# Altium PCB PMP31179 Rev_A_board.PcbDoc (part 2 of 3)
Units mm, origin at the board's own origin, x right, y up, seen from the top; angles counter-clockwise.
Board outline 218.44 x 102.26 mm, 4 copper layers (Top Layer, Mid-Layer 1, Mid-Layer 2, Bottom Layer), stack 1.473 mm thick; 246 components, 120 nets, 592 pads, 115 vias.
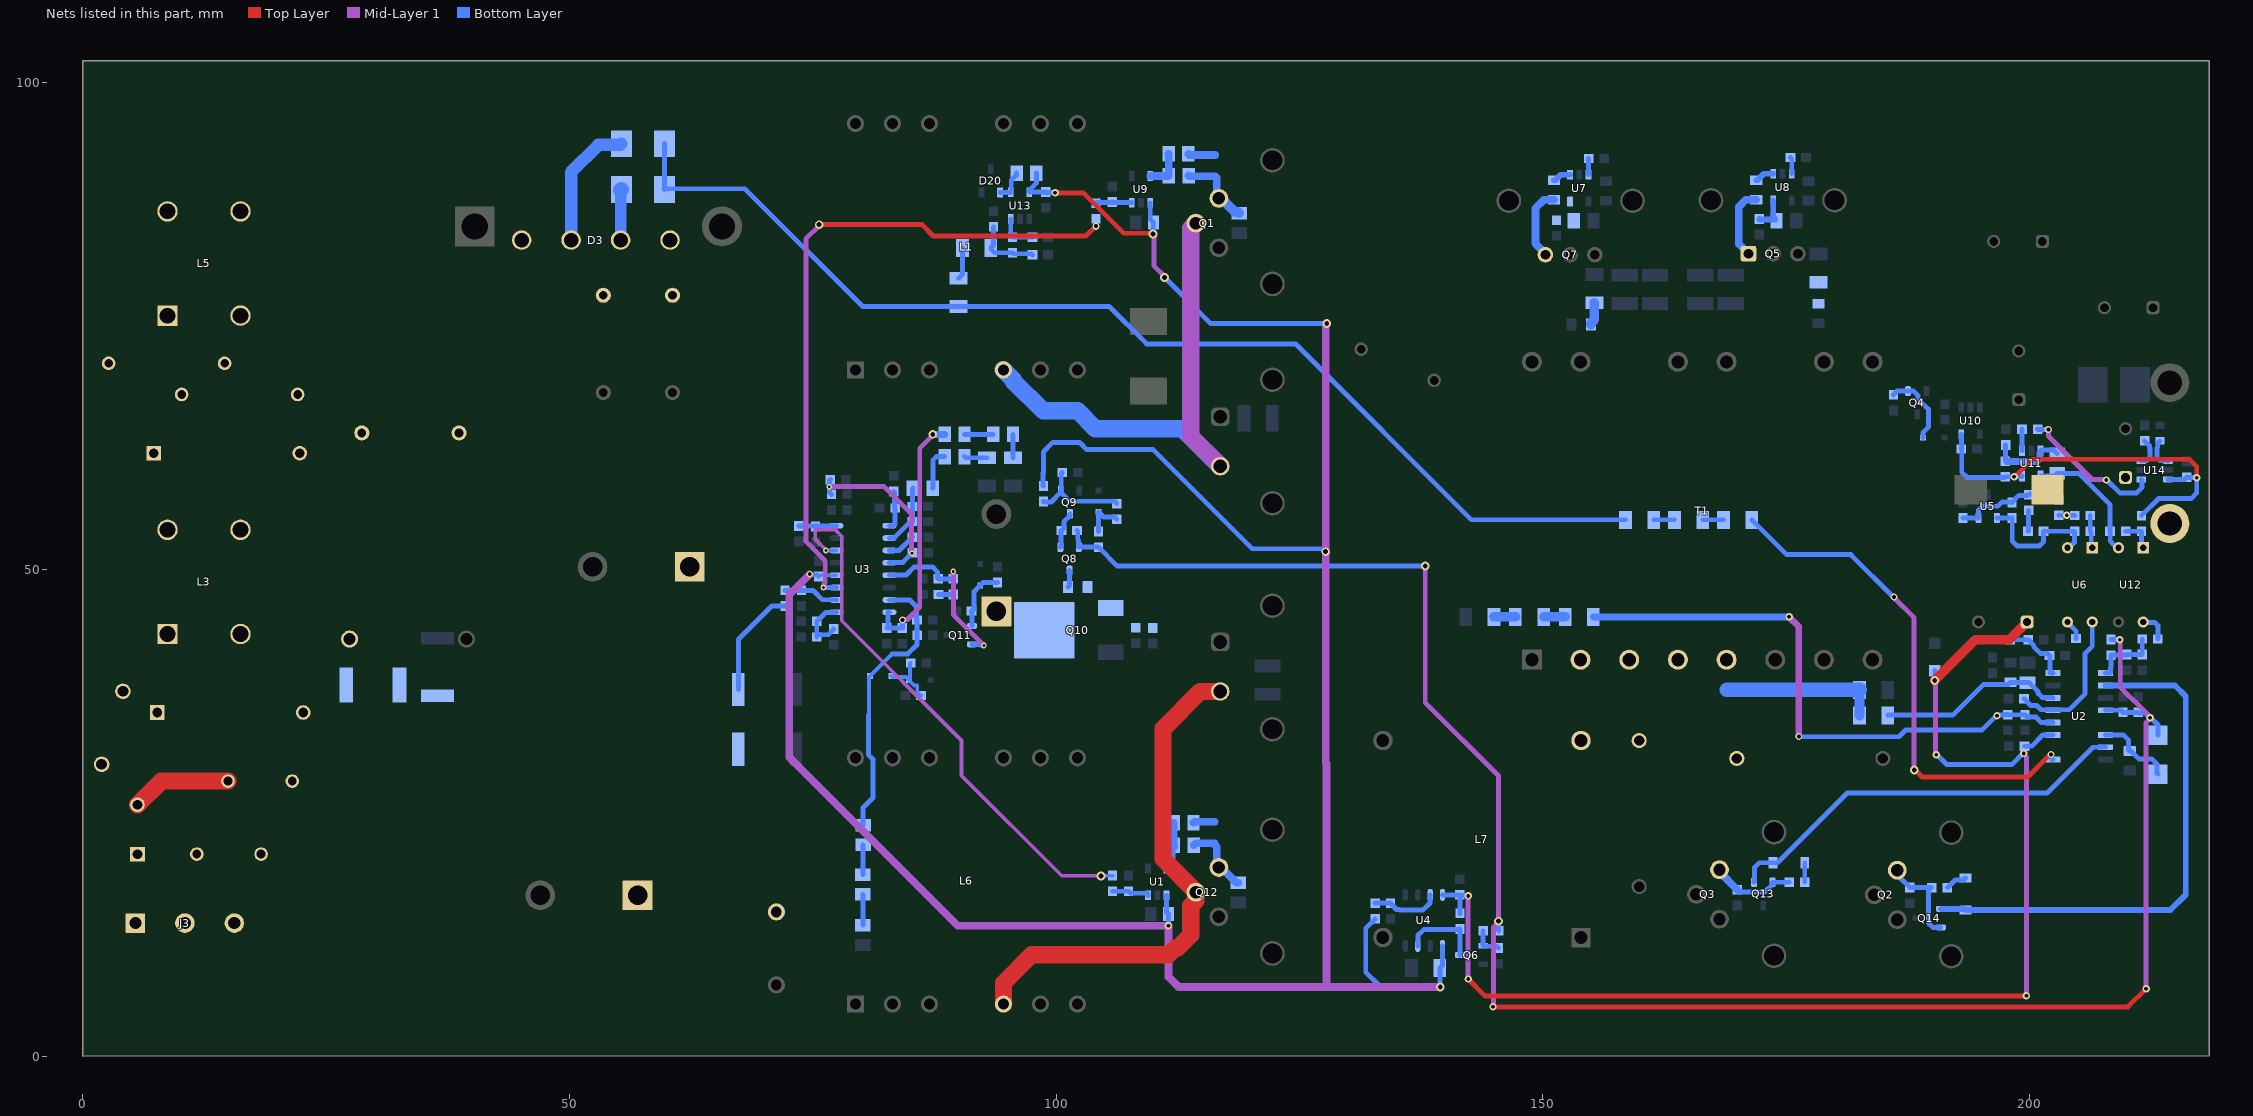
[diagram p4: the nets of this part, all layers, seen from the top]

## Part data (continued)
D20: library part CMP-0033016-1, "Precision Micropower Shunt Voltage Reference, 1% accuracy, 5 V, 15 ppm / degC, 15 mA, -40 to 125 degC, 3-pin SOT-23 (DBZ), Green (RoHS & no Sb/Br)", Manufacturer="Texas Instruments", Rating=Catalog, Temp Coeff(Max)(ppm/ degree C)=150, Temp Coeff(Typ)(ppm/ degree C)=15
D100: library part CMP-0082070-2, "Diode, Switching, 600 V, 3 A, SMC", Manufacturer=Vishay-Semiconductor, Value2=1.15V
F1: "FUSE, BOARD MOUNT, 10 A, 300 V, TH-2P", Manufacturer="LITTELFUSE INC"
H1 H2 H3 H4 H5 H6: library part CMP-0003620-1, "Bumpon, Hemisphere, 0.44 X 0.20, Clear", Manufacturer=3M, PartNumber="SJ-5303 (CLEAR)", Supplier Part Number 1=SJ5303-7-ND
H7: library part CMP-0092962-1, "Heat Sink 11 K/W, 25,4x42x25 mm, black anodized, for TO-220", Manufacturer="Assmann WSW components", Mating Package=TO-220, Operating Temperature Range=to, Thermal Resistance Forced Air Flow=11°C/W
J3: library part CMP-0074911-1, "Terminal Block, 5.08 mm, 3x1, Brass, TH", Color=Blue, Current_A=15A, Manufacturer="On-Shore Technology", Supplier Part Number 1=ED1610-ND, Voltage_V=300V
L1 L6: library part CMP-0088743-1, "INDUCTOR", Manufacturer="Wurth Electronics", Operating Temperature Range="-40°C to +125°C", Voltage_Isolation_Vrms=1kV
L2: library part CMP-0064735-2, "Inductor, Toroid, Powdered Iron, 150 uH, 5 A, 0.045 ohm, TH", Manufacturer="Wurth Elektronik", Supplier Part Number 1=732-1427-ND, Value1="0.045 ohm", Value2=5A, ValueDisplayed=150uH
L3 L5: "FILTER, WE-CMBNC COMMON MODE POWER LINE CHOKE, 1mH, 15A, VERTICAL, TH-4P", Manufacturer="Wurth Elektronics"
L4: library part CMP-0062077-1, "Inductor, Ferrite, 300 nH, 32 A, 0.00031 ohm, SMD", Manufacturer="Pulse Engineering", Supplier Part Number 1=553-2161-1-ND, Value1="0.00031 ohm", Value2=32A, ValueDisplayed=300nH
L7: library part CMP-0088744-1, "INDUCTOR, 17uH, 20A", Manufacturer="Wurth Electronics", Operating Temperature Range="-40°C to +125°C", Test Frequency=10kHz, Tolerance_%=10%
L8: library part CMP-0064496-2, "Inductor, Drum Core, Ferrite, 22 uH, 0.7 A, 0.255 ohm, SMD", Manufacturer="Wurth Elektronik", Supplier Part Number 1=732-1337-1-ND, Value1="0.255 ohm", Value2=0.7A, ValueDisplayed=22uH
Logo2: library part CMP-0074840-1, "ESD Susceptible Symbol"
Logo3 LOGO9: library part CMP-0074837-1, "IEC 61010-1 Hot Surface Warning"
LOGO4 LOGO7 LOGO8 LOGO10: library part CMP-0074835-1, "IEC 61010-1 High Voltage Warning"
M1 M2 M3 M4 M5 M6 M7 M8: "HEATSINK, ALUMINIUM WITH CLIP, VERTICAL MOUNT, SOLDERABLE PIN, TO-220", Manufacturer=OHMITE
Q1 Q12: library part CMP-0001223-3, "MOSFET N-CHANNEL 600V 26A TO220", Alternate Manufacturer=None, Manufacturer="Infineon Technologies", Supplier Part Number 1=IPA60R120P7XKSA1-ND, Value2="37 nC"
Q2 Q3: library part CMP-0001223-3, "MOSFET N-CHANNEL 600V 26A TO220", Alternate Manufacturer=None, Manufacturer="Infineon Technologies", PartNumber=IPP60R070CFD7XKSA1, Supplier Part Number 1=IPP60R070CFD7XKSA1-ND, Value2="65 nC"
Q4: library part CMP-0000488-2, "Transistor, NPN, 60 V, 0.5 A, AEC-Q101, SOT-23", Manufacturer="ON Semiconductor", Supplier Part Number 1=MMBTA05LT1GOSCT-ND, Value1="0.5 A"
Q5 Q7: library part CMP-0000955-2, "MOSFET, N-CH, 100 V, 100 A, KCS0003B (TO-220-3)", Alternate Manufacturer=None, Manufacturer="Texas Instruments", Supplier Part Number 1=296-37480-5-ND, Value2="38 nC"
Q6: library part CMP-0000421-2, "Transistor, NPN, 30 V, 0.6 A, SOT-23", Manufacturer="ON Semiconductor", Supplier Part Number 1=MMBT2222LT1GOSCT-ND, Value1="0.6 A", Value2=300
Q8: library part CMP-0000011-2, "MOSFET, P-CH, -50 V, -0.13 A, SOT-23", Alternate Manufacturer=None, Manufacturer="Diodes Inc.", Supplier Part Number 1=BSS84-FDICT-ND
Q9: library part CMP-0000419-1, "Transistor, NPN, 40 V, 0.2 A, SOT-23", Manufacturer="ON Semiconductor", Supplier Part Number 1=MMBT3904LT1GOSCT-ND, Value1="0.2 A", Value2=300
Q10: library part CMP-0079555-2, "MOSFET, N-CH, 600 V, 9 A, DPAK", Alternate Manufacturer=None, Manufacturer="Infineon Technologies", Supplier Part Number 1=IPD60R360P7SAUMA1CT-ND, Value1="? ohm", Value2="13 nC"
Q11: library part CMP-0000326-1, "Transistor, PNP, 40 V, 0.2 A, SOT-23", Manufacturer="Diodes Inc.", Supplier Part Number 1=MMBT3906-FDICT-ND, Value1="0.2 A", Value2=400
Q13 Q14: library part CMP-0000317-2, "Transistor, PNP, 30 V, 0.1 A, SOT-23", Manufacturer="Diodes Inc.", Supplier Part Number 1=BC858C-7-F-ND, Value1="0.1 A", Value2=600
R1 R11: library part CMP-0023343-3, "RES, 0, 1%, 0.1 W, AEC-Q200 Grade 0, 0603", Manufacturer="Stackpole Electronics Inc", Power_W=100mW, Supplier Part Number 1=RMCF0603ZT0R00CT-ND, TempCo=ppm/C, Tolerance_%=1%, Value2=0.1W, Value_Code=0
R2: library part CMP-0022703-3, "RES, 4.53 k, 1%, 0.1 W, AEC-Q200 Grade 0, 0603", Manufacturer=Panasonic, Power_W=100mW, Supplier Part Number 1=P4.53KHCT-ND, TempCo="100 ppm/C", Tolerance_%=1%, Value2=0.1W, Value_Code=4k53, ValueDisplayed=4.53k
R3: library part CMP-0020904-3, "RES, 150, 1%, 0.125 W, AEC-Q200 Grade 0, 0805", Manufacturer=Vishay-Dale, Power_W=125mW, Supplier Part Number 1=541-150CCT-ND, TempCo="100 ppm/C", Tolerance_%=1%, Value2=0.125W, Value_Code=150R, ValueDisplayed=150
R4 R54: library part CMP-0020655-3, "RES, 18, 5%, 0.125 W, AEC-Q200 Grade 0, 0805", Manufacturer=Panasonic, Power_W=125mW, Supplier Part Number 1=P18ACT-ND, TempCo="200 ppm/C", Tolerance_%=5%, Value2=0.125W, Value_Code=18R0, ValueDisplayed=18
R5: library part CMP-0020941-3, "RES, 18.2, 1%, 0.125 W, AEC-Q200 Grade 0, 0805", Manufacturer=Vishay-Dale, PartNumber=CRCW080518R2FKEA, Power_W=125mW, Supplier Part Number 1=541-18.2CCT-ND, TempCo="100 ppm/C", Tolerance_%=1%, Value2=0.125W, Value_Code=18R2, ValueDisplayed=18.2
R6 R19 R74: library part CMP-0020842-3, "RES, 10.0 k, 1%, 0.125 W, AEC-Q200 Grade 0, 0805", Manufacturer=Vishay-Dale, PartNumber=CRCW080510K0FKEA, Power_W=125mW, Supplier Part Number 1=541-10.0KCCT-ND, TempCo="100 ppm/C", Tolerance_%=1%, Value2=0.125W, Value_Code=10k0, ValueDisplayed=10.0k
R7 R8: library part CMP-0015775-2, "RES, 0.03, 1%, 2 W, 2512", Manufacturer="Stackpole Electronics Inc", PartNumber=CSRN2512FK30L0, Power_W=2W, Supplier Part Number 1=CSRN2512FK30L0CT-ND, TempCo="200 ppm/C", Tolerance_%=1%, Value_Code=R030, ValueDisplayed=0.03
R9: library part CMP-0022426-4, "RES, 44.2 k, 1%, 0.1 W, AEC-Q200 Grade 0, 0603", Manufacturer=Vishay-Dale, Power_W=100mW, Supplier Part Number 1=541-44.2KHCT-ND, TempCo="100 ppm/C", Tolerance_%=1%, Value2=0.1W, Value_Code=44k2, ValueDisplayed=44.2k
R10 R22 R31: library part CMP-0016687-3, "RES, 1.00 k, 1%, 0.25 W, AEC-Q200 Grade 0, 1206", Manufacturer=Vishay-Dale, PartNumber=CRCW12061K00FKEA, Power_W=250mW, Supplier Part Number 1=541-1.00KFCT-ND, TempCo="100 ppm/C", Tolerance_%=1%, Value2=0.25W, Value_Code=1k00, ValueDisplayed=1.00k
R12: library part CMP-0023306-5, "RES, 8.06 k, 1%, 0.1 W, 0603", Manufacturer=Yageo, Power_W=100mW, Supplier Part Number 1=311-8.06KHRCT-ND, TempCo="100 ppm/C", Tolerance_%=1%, Value2=0.1W, Value_Code=8k06, ValueDisplayed=8.06k
R13 R57: library part CMP-0020812-2, "RES, 2.2, 5%, 0.125 W, 0805", Manufacturer="Yageo America", Power_W=125mW, Supplier Part Number 1=311-2.2ARCT-ND, TempCo="200 ppm/C", Tolerance_%=5%, Value2=0.125W, Value_Code=2R20, ValueDisplayed=2.2
R14: library part CMP-0022705-3, "RES, 49.9 k, 1%, 0.1 W, AEC-Q200 Grade 0, 0603", Manufacturer=Panasonic, Power_W=100mW, Supplier Part Number 1=P49.9KHCT-ND, TempCo="100 ppm/C", Tolerance_%=1%, Value2=0.1W, Value_Code=49k9, ValueDisplayed=49.9k
R15 R79: library part CMP-0021990-4, "RES, 100 k, 1%, 0.1 W, AEC-Q200 Grade 0, 0603", Manufacturer=Vishay-Dale, Power_W=100mW, Supplier Part Number 1=541-100KHCT-ND, TempCo="100 ppm/C", Tolerance_%=1%, Value2=0.1W, Value_Code=100k
R16: library part CMP-0023118-5, "RES, 44.2 k, 1%, 0.1 W, 0603", Manufacturer=Yageo, Power_W=100mW, Supplier Part Number 1=311-44.2KHRCT-ND, TempCo="100 ppm/C", Tolerance_%=1%, Value2=0.1W, Value_Code=44k2, ValueDisplayed=44.2k
R17: library part CMP-0022779-5, "RES, 12.0 k, 1%, 0.1 W, 0603", Manufacturer=Yageo, Power_W=100mW, Supplier Part Number 1=311-12.0KHRCT-ND, TempCo="100 ppm/C", Tolerance_%=1%, Value2=0.1W, Value_Code=12k0, ValueDisplayed=12.0k
R18: library part CMP-0022482-4, "RES, 51.1 k, 1%, 0.1 W, AEC-Q200 Grade 0, 0603", Manufacturer=Vishay-Dale, Power_W=100mW, Supplier Part Number 1=541-51.1KHCT-ND, TempCo="100 ppm/C", Tolerance_%=1%, Value2=0.1W, Value_Code=51k1, ValueDisplayed=51.1k
R20: library part CMP-0018672-3, "RES, 3.0 M, 5%, 0.25 W, AEC-Q200 Grade 0, 1206", Manufacturer=Vishay-Dale, Power_W=250mW, Supplier Part Number 1=541-3.0MECT-ND, TempCo="200 ppm/C", Tolerance_%=5%, Value2=0.25W, Value_Code=3M00, ValueDisplayed=3.0M
R21 R23 R33: library part CMP-0021895-2, "RES, 2.20 M, 1%, 0.125 W, 0805", Manufacturer="Yageo America", Power_W=125mW, Supplier Part Number 1=311-2.20MCRCT-ND, TempCo="100 ppm/C", Tolerance_%=1%, Value2=0.125W, Value_Code=2M20, ValueDisplayed=2.20M
R24 R26: library part CMP-0022563-4, "RES, 6.81 k, 1%, 0.1 W, AEC-Q200 Grade 0, 0603", Manufacturer=Vishay-Dale, Power_W=100mW, Supplier Part Number 1=541-6.81KHCT-ND, TempCo="100 ppm/C", Tolerance_%=1%, Value2=0.1W, Value_Code=6k81, ValueDisplayed=6.81k
R25: library part CMP-0024929-2, "RES, 213 k, 0.5%, 0.1 W, 0603", Manufacturer="Yageo America", Power_W=100mW, TempCo="50 ppm/C", Tolerance_%=0.5%, Value2=0.1W, Value_Code=213k
R27 R34 R46 R86: library part CMP-0021137-3, "RES, 2.74 M, 1%, 0.125 W, AEC-Q200 Grade 0, 0805", Manufacturer=Vishay-Dale, PartNumber=CRCW08052M74FKEA, Power_W=125mW, Supplier Part Number 1=541-2.74MCCT-ND, TempCo="100 ppm/C", Tolerance_%=1%, Value2=0.125W, Value_Code=2M74, ValueDisplayed=2.74M
R28 R77: library part CMP-0017050-3, "RES, 511 k, 1%, 0.25 W, AEC-Q200 Grade 0, 1206", Manufacturer=Vishay-Dale, PartNumber=CRCW1206511KFKEA, Power_W=250mW, Supplier Part Number 1=541-511KFCT-ND, TempCo="100 ppm/C", Tolerance_%=1%, Value2=0.25W, Value_Code=511k
R29 R36: library part CMP-0018656-3, "RES, 330 k, 5%, 0.25 W, AEC-Q200 Grade 0, 1206", Manufacturer=Vishay-Dale, PartNumber=CRCW1206330KJNEA, Power_W=250mW, Supplier Part Number 1=541-330KECT-ND, TempCo="200 ppm/C", Tolerance_%=5%, Value2=0.25W, Value_Code=330k
R30: library part CMP-0021991-4, "RES, 100, 1%, 0.1 W, AEC-Q200 Grade 0, 0603", Manufacturer=Vishay-Dale, PartNumber=CRCW0603100RFKEA, Power_W=100mW, Supplier Part Number 1=541-100HCT-ND, TempCo="100 ppm/C", Tolerance_%=1%, Value2=0.1W, Value_Code=100R, ValueDisplayed=100
R32: library part CMP-0022768-4, "RES, 120 k, 1%, 0.1 W, 0603", Manufacturer=Yageo, Power_W=100mW, Supplier Part Number 1=311-120KHRCT-ND, TempCo="100 ppm/C", Tolerance_%=1%, Value2=0.1W, Value_Code=120k
R35: library part CMP-0024931-3, "RES, 215 k, 0.5%, 0.1 W, 0603", Manufacturer="Yageo America", Power_W=100mW, TempCo="50 ppm/C", Tolerance_%=0.5%, Value2=0.1W, Value_Code=215k
R37: library part CMP-0022093-4, Power_W=100mW, TempCo="100 ppm/C", Tolerance_%=1%, Value2=0.1W
R38 R40: library part CMP-0025758-4, "RES, 22, 5%, 0.1 W, AEC-Q200 Grade 0, 0603", Manufacturer=Vishay-Dale, PartNumber=CRCW060322R0JNEA, Power_W=100mW, Supplier Part Number 1=541-22GCT-ND, TempCo="200 ppm/C", Tolerance_%=5%, Value2=0.1W, Value_Code=22R0, ValueDisplayed=22
R39: library part CMP-0022901-4, "RES, 200 k, 1%, 0.1 W, 0603", Manufacturer=Yageo, Power_W=100mW, Supplier Part Number 1=311-200KHRCT-ND, TempCo="100 ppm/C", Tolerance_%=1%, Value2=0.1W, Value_Code=200k
R41: library part CMP-0022616-4, "RES, 80.6 k, 1%, 0.1 W, AEC-Q200 Grade 0, 0603", Manufacturer=Vishay-Dale, Power_W=100mW, Supplier Part Number 1=541-80.6KHCT-ND, TempCo="100 ppm/C", Tolerance_%=1%, Value2=0.1W, Value_Code=80k6, ValueDisplayed=80.6k
R42: library part CMP-0022966-5, "RES, 27.0 k, 1%, 0.1 W, 0603", Manufacturer=Yageo, Power_W=100mW, Supplier Part Number 1=311-27.0KHRCT-ND, TempCo="100 ppm/C", Tolerance_%=1%, Value2=0.1W, Value_Code=27k0, ValueDisplayed=27.0k
R43: library part CMP-0018656-2, "RES, 330 k, 5%, 0.25 W, 1206", Manufacturer=Vishay-Dale, Power_W=250mW, Supplier Part Number 1=541-330KECT-ND, TempCo="200 ppm/C", Tolerance_%=5%, Value2=0.25W, Value_Code=330k
R44 R45: library part CMP-0025696-3, "RES, 4.7 k, 5%, 0.1 W, 0603", Manufacturer=Bourns, PartNumber=CR0603-JW-472GLF, Power_W=100mW, Supplier Part Number 1=CR0603-JW-472GLFCT-ND, TempCo="200 ppm/C", Tolerance_%=5%, Value2=0.1W, Value_Code=4k70, ValueDisplayed=4.7k
R47 R71 R73: library part CMP-0022558-4, "RES, 6.04 k, 1%, 0.1 W, AEC-Q200 Grade 0, 0603", Manufacturer=Vishay-Dale, PartNumber=CRCW06036K04FKEA, Power_W=100mW, Supplier Part Number 1=541-6.04KHCT-ND, TempCo="100 ppm/C", Tolerance_%=1%, Value2=0.1W, Value_Code=6k04, ValueDisplayed=6.04k
R48: library part CMP-0022052-4, "RES, 147 k, 1%, 0.1 W, AEC-Q200 Grade 0, 0603", Manufacturer=Vishay-Dale, PartNumber=CRCW0603147KFKEA, Power_W=100mW, Supplier Part Number 1=541-147KHCT-ND, TempCo="100 ppm/C", Tolerance_%=1%, Value2=0.1W, Value_Code=147k
R49: library part CMP-0021998-4, "RES, 10.0 k, 1%, 0.1 W, AEC-Q200 Grade 0, 0603", Manufacturer=Vishay-Dale, PartNumber=CRCW060310K0FKEA, Power_W=100mW, Supplier Part Number 1=541-10.0KHCT-ND, TempCo="100 ppm/C", Tolerance_%=1%, Value2=0.1W, Value_Code=10k0, ValueDisplayed=10.0k
R50: library part CMP-0022790-5, "RES, 13.3 k, 1%, 0.1 W, 0603", Manufacturer=Yageo, Power_W=100mW, Supplier Part Number 1=311-13.3KHRCT-ND, TempCo="100 ppm/C", Tolerance_%=1%, Value2=0.1W, Value_Code=13k3, ValueDisplayed=13.3k
R51 R63: library part CMP-0022010-4, "RES, 113 k, 1%, 0.1 W, AEC-Q200 Grade 0, 0603", Manufacturer=Vishay-Dale, Power_W=100mW, Supplier Part Number 1=541-113KHCT-ND, TempCo="100 ppm/C", Tolerance_%=1%, Value2=0.1W, Value_Code=113k
R52 R53: library part CMP-0020448-3, "RES, 10, 5%, 0.125 W, AEC-Q200 Grade 0, 0805", Manufacturer=Vishay-Dale, PartNumber=CRCW080510R0JNEA, Power_W=125mW, Supplier Part Number 1=541-10ACT-ND, TempCo="200 ppm/C", Tolerance_%=5%, Value2=0.125W, Value_Code=10R0, ValueDisplayed=10
R55 R64: library part CMP-0023626-3, "RES, 10.0 k, 0.01%, 0.063 W, 0603", Manufacturer="Stackpole Electronics Inc", PartNumber=RNCF0603TKY10K0, Power_W=63mW, Supplier Part Number 1=RNCF0603TKY10K0CT-ND, TempCo="5 ppm/C", Tolerance_%=0.01%, Value2=0.063W, Value_Code=10k0, ValueDisplayed=10.0k
R56: library part CMP-0023630-3, "RES, 100 k, 0.1%, 0.1 W, 0603", Manufacturer="Yageo America", Power_W=100mW, Supplier Part Number 1=603-RT0603BRD07100KL, TempCo="25 ppm/C", Tolerance_%=0.1%, Value2=0.1W, Value_Code=100k
R58 R59: library part CMP-0022679-3, "RES, 100, 1%, 0.1 W, AEC-Q200 Grade 0, 0603", Manufacturer=Panasonic, Power_W=100mW, Supplier Part Number 1=P100HCT-ND, TempCo="100 ppm/C", Tolerance_%=1%, Value2=0.1W, Value_Code=100R, ValueDisplayed=100
R60 R61: library part CMP-0020563-3, "RES, 4.7, 5%, 0.125 W, AEC-Q200 Grade 0, 0805", Manufacturer=Vishay-Dale, PartNumber=CRCW08054R70JNEA, Power_W=125mW, Supplier Part Number 1=541-4.7ACT-ND, TempCo="200 ppm/C", Tolerance_%=5%, Value2=0.125W, Value_Code=4R70, ValueDisplayed=4.7
R62: library part CMP-0023252-5, "RES, 6.81 k, 1%, 0.1 W, 0603", Manufacturer=Yageo, Power_W=100mW, Supplier Part Number 1=311-6.81KHRCT-ND, TempCo="100 ppm/C", Tolerance_%=1%, Value2=0.1W, Value_Code=6k81, ValueDisplayed=6.81k
R65: library part CMP-0015849-2, "RES, 0.0005, 1%, 2 W, 2512", Manufacturer=Vishay-Dale, Power_W=2W, TempCo="400 ppm/C", Tolerance_%=1%, Value_Code=L5000, ValueDisplayed=0.0005
R66 R78: library part CMP-0022004-4, "RES, 10.0, 1%, 0.25 W, AEC-Q200 Grade 0, 0603", Manufacturer=Vishay-Dale, Power_W=250mW, Supplier Part Number 1=541-10.0SCT-ND, TempCo="100 ppm/C", Tolerance_%=1%, Value2=0.25W, Value_Code=10R0, ValueDisplayed=10.0
R67: library part CMP-0020980-3, "RES, 1.00 M, 1%, 0.125 W, AEC-Q200 Grade 0, 0805", Manufacturer=Vishay-Dale, Power_W=125mW, Supplier Part Number 1=541-1.00MCCT-ND, TempCo="100 ppm/C", Tolerance_%=1%, Value2=0.125W, Value_Code=1M00, ValueDisplayed=1.00M
R68: library part CMP-0022731-2, "RES, 1.00 M, 1%, 0.125 W, 0603", Manufacturer=Vishay/Beyschlag, Power_W=125mW, Supplier Part Number 1=MCT0603-1.00M-CFCT-ND, TempCo="50 ppm/C", Tolerance_%=1%, Value2=0.125W, Value_Code=1M00, ValueDisplayed=1.00M
R69: library part CMP-0022697-2, "RES, 330 k, 1%, 0.1 W, AEC-Q200 Grade 0, 0603", Manufacturer=Panasonic, Power_W=100mW, Supplier Part Number 1=P330KHCT-ND, TempCo="100 ppm/C", Tolerance_%=1%, Value2=0.1W, Value_Code=330k
R70: library part CMP-0022441-4, "RES, 487 k, 1%, 0.1 W, AEC-Q200 Grade 0, 0603", Manufacturer=Vishay-Dale, PartNumber=CRCW0603487KFKEA, Power_W=100mW, Supplier Part Number 1=541-487KHCT-ND, TempCo="100 ppm/C", Tolerance_%=1%, Value2=0.1W, Value_Code=487k
R72: library part CMP-0024961-3, "RES, 234 k, 0.5%, 0.1 W, 0603", Manufacturer="Yageo America", Power_W=100mW, TempCo="50 ppm/C", Tolerance_%=0.5%, Value2=0.1W, Value_Code=234k
R75: library part CMP-0022142-4, "RES, 1.10 M, 1%, 0.1 W, AEC-Q200 Grade 0, 0603", Manufacturer=Vishay-Dale, Power_W=100mW, Supplier Part Number 1=541-1.10MHCT-ND, TempCo="100 ppm/C", Tolerance_%=1%, Value2=0.1W, Value_Code=1M10, ValueDisplayed=1.10M
R76: library part CMP-0022651-4, "RES, 90.9 k, 1%, 0.1 W, AEC-Q200 Grade 0, 0603", Manufacturer=Vishay-Dale, Power_W=100mW, Supplier Part Number 1=541-90.9KHCT-ND, TempCo="100 ppm/C", Tolerance_%=1%, Value2=0.1W, Value_Code=90k9, ValueDisplayed=90.9k
R80: library part CMP-0023267-5, "RES, 75.0 k, 1%, 0.1 W, 0603", Manufacturer=Yageo, Power_W=100mW, Supplier Part Number 1=311-75.0KHRCT-ND, TempCo="100 ppm/C", Tolerance_%=1%, Value2=0.1W, Value_Code=75k0, ValueDisplayed=75.0k
R81: library part CMP-0025792-4, "RES, 390 k, 5%, 0.1 W, AEC-Q200 Grade 0, 0603", Manufacturer=Vishay-Dale, Power_W=100mW, Supplier Part Number 1=541-390KGCT-ND, TempCo="200 ppm/C", Tolerance_%=5%, Value2=0.1W, Value_Code=390k
R82: library part CMP-0023142-5, "RES, 49.9 k, 1%, 0.1 W, 0603", Manufacturer=Yageo, Power_W=100mW, Supplier Part Number 1=311-49.9KHRCT-ND, TempCo="100 ppm/C", Tolerance_%=1%, Value2=0.1W, Value_Code=49k9, ValueDisplayed=49.9k
R83: library part CMP-0022692-3, "RES, 22.0 k, 1%, 0.1 W, AEC-Q200 Grade 0, 0603", Manufacturer=Panasonic, Power_W=100mW, Supplier Part Number 1=P22.0KHCT-ND, TempCo="100 ppm/C", Tolerance_%=1%, Value2=0.1W, Value_Code=22k0, ValueDisplayed=22.0k
R87: library part CMP-0018647-3, "RES, 2.7 M, 5%, 0.25 W, AEC-Q200 Grade 0, 1206", Manufacturer=Vishay-Dale, Power_W=250mW, Supplier Part Number 1=541-2.7MECT-ND, TempCo="200 ppm/C", Tolerance_%=5%, Value2=0.25W, Value_Code=2M70, ValueDisplayed=2.7M
R88: library part CMP-0022663-4, "RES, 97.6 k, 1%, 0.1 W, AEC-Q200 Grade 0, 0603", Manufacturer=Vishay-Dale, Power_W=100mW, Supplier Part Number 1=541-97.6KHCT-ND, TempCo="100 ppm/C", Tolerance_%=1%, Value2=0.1W, Value_Code=97k6, ValueDisplayed=97.6k
R89: library part CMP-0023292-5, "RES, 82.0 k, 1%, 0.1 W, 0603", Manufacturer=Yageo, Power_W=100mW, Supplier Part Number 1=311-82.0KHRCT-ND, TempCo="100 ppm/C", Tolerance_%=1%, Value2=0.1W, Value_Code=82k0, ValueDisplayed=82.0k
R90: library part CMP-0022036-4, "RES, 130 k, 1%, 0.1 W, AEC-Q200 Grade 0, 0603", Manufacturer=Vishay-Dale, Power_W=100mW, Supplier Part Number 1=541-130KHCT-ND, TempCo="100 ppm/C", Tolerance_%=1%, Value2=0.1W, Value_Code=130k
R91: library part CMP-0015970-3, "RES, 47, 5%, 1 W, AEC-Q200 Grade 0, 2512", Manufacturer=Vishay-Dale, Power_W=1W, Supplier Part Number 1=541-47XCT-ND, TempCo="200 ppm/C", Tolerance_%=5%, Value_Code=47R0, ValueDisplayed=47
R100 R101: library part CMP-0022680-4, "RES, 1.00 k, 1%, 0.1 W, 0603", Manufacturer=Panasonic, Power_W=100mW, Supplier Part Number 1=P1.00KHCT-ND, TempCo="100 ppm/C", Tolerance_%=1%, Value2=0.1W, Value_Code=1k00, ValueDisplayed=1.00k
RT1: library part CMP-0002554-2, "Thermistor NTC, 22 ohm, 20%, 15x7mm", Manufacturer=TDK, Power_W=3.1W, Supplier Part Number 1=495-3054-ND, Tolerance_%=20%
RV1: library part CMP-0002100-2, "Varistor 275V RMS 10MM Radial, TH", Manufacturer=TDK, PartNumber=S10K275E2, Supplier Part Number 1=495-1433-ND
T1: library part CMP-0088745-1, "TRANSFORMER", Frequency_Fixed=100kHz, Manufacturer="Wurth Electronics", Operating Temperature Range="-40°C to +125°C", Voltage_Isolation_Vrms=3kV
U1 U9: library part CMP-0066947-1, "4A/4A Single Channel High-speed Low-side Gate Driver, DBV0005A (SOT-23-5)", Alternate Manufacturer="Texas Instruments", Alternate PartNumber=UCC27517DBVT
U2: library part CMP-0013274-1, "Enhanced LLC Resonant Controller with Driver, DDB0014A (SOIC-14)", Alternate Manufacturer="Texas Instruments"
U3: library part CMP-0065070-5, "Natural Interleaving Transition Mode PFC Controller with Improved Light Load Efficiency, D0016A (SOIC-16)", Alternate Manufacturer="Texas Instruments", Alternate PartNumber=UCC28064AD
U4: library part CMP-0076214-1, "Series of Adjustable Micropower Voltage Regulators, D0008A (SOIC-8)", Alternate Manufacturer="Texas Instruments", Alternate PartNumber=LP2951ACM/NOPB
U5: library part CMP-0084729-1, "Programmable Shunt Regulator with Optimized Reference Current, DBZ0003A (SOT-23-3)", Alternate Manufacturer="Texas Instruments"
U6: library part CMP-0006187-3, "Optocoupler, 5.3 kV, 50-600% CTR, TH", Manufacturer=Vishay-Semiconductor, PartNumber=VO618A-3, Supplier Part Number 1=VO618A-3-ND, Voltage_Isolation_Vrms=5.3kV
U7 U8: library part CMP-0013050-3, "High-Frequency Multi-Mode Synchronous Rectifier Controller, DBV0005A (SOT-23-5)", Alternate Manufacturer="Texas Instruments", Alternate PartNumber=UCC24612-1DBVT
U10: library part CMP-0070878-1, "Micropower 100 mA Ultra Low-Dropout Regulator, 5-pin SOT-23, Pb-Free", Manufacturer="Texas Instruments", PackageTopMarking=L05B*XTT, PartNumber=LP2981-50DBVR, PowerWise=N
U11: library part CMP-0089970-1, "Single Differential Comparator", Input Bias Current=-0.0035uA, Input Offset Voltage=0.37mV, Manufacturer="Texas Instruments", Max Supply Voltage=36V, Min Supply Voltage=3V, Nominal Supply Current=210-275uA, Operating Temperature Range="-40°C to +105°C", Output Current Per Channel=20mA, Voltage Gain=200V/mV
U12: library part CMP-0006187-3, "Optocoupler, 5.3 kV, 50-600% CTR, TH", Manufacturer=Vishay-Semiconductor, PartNumber=VO618A, Supplier Part Number 1=VO618A-ND, Voltage_Isolation_Vrms=5.3kV
U13: library part CMP-0073526-1, "36V, Low-Power, RRO, General-Purpose Operational Amplifier, DBV0005A (SOT-23-5)", Alternate Manufacturer="Texas Instruments", Alternate PartNumber=TLV171IDBVT
U14: library part CMP-0013228-2, "Bidirectional, Low- and High-Side Measurement, Multichannel, Voltage Output, Current-Sense Amplifier, DBV0006A (SOT-6)", Alternate Manufacturer="Texas Instruments"

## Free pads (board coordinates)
  round 4 hole 2.5: 1(214.397,54.73) 1(214.397,69.208)

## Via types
v1: diameter 0.762, hole 0.381, Top Layer to Bottom Layer, 47 vias
v2: diameter 0.9, hole 0.5, Top Layer to Bottom Layer, 18 vias
v3: diameter 0.762, hole 0.381, Top Layer to Bottom Layer, tented bottom, 17 vias
v4: diameter 0.9, hole 0.5, Top Layer to Bottom Layer, tented bottom, 7 vias
v5: diameter 0.6, hole 0.3, Top Layer to Bottom Layer, tented bottom, 5 vias
v6: diameter 0.762, hole 0.381, Top Layer to Bottom Layer, tented both sides, 5 vias
v7: diameter 0.9, hole 0.5, Top Layer to Bottom Layer, tented top, 4 vias
v8: diameter 0.7, hole 0.4, Top Layer to Bottom Layer, tented bottom, 4 vias
v9: diameter 0.6, hole 0.3, Top Layer to Bottom Layer, 4 vias
v10: diameter 0.7, hole 0.4, Top Layer to Bottom Layer, tented top, 1 vias
v11: diameter 0.9, hole 0.5, Top Layer to Bottom Layer, tented both sides, 1 vias
v12: diameter 0.7/0.7/0.7/0.7 (per signal layer), hole 0.4, Top Layer to Bottom Layer, 1 vias
v13: diameter 0.762, hole 0.381, Top Layer to Bottom Layer, tented top, 1 vias

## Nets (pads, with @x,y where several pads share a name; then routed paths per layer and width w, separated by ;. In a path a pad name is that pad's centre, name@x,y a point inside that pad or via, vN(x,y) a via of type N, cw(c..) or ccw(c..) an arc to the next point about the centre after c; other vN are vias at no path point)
5V: C56.1 C57.1 R68.2 R71.2 U10.5 U11.5 U14.6 | length 42.6
  Top Layer w0.5: v3(198.395,59.54) 198.466,59.54 200.268,61.342 216.398,61.342 217.17,60.57 v1(217.17,59.44)
  Bottom Layer w0.5: C56.1@192.978,62.378 193.029,62.328 193.029,60.008 193.567,59.47 197.44,59.47 R68.2@197.503,59.533 197.507,59.537 198.392,59.537 v3(198.395,59.54) 198.433,59.578 199.188,59.578 U11.5@199.225,59.615 ; C56.1@192.978,62.378 U10.5@192.979,63.899 ; R71.2@211.502,55.543 211.502,55.568 213.231,57.298 216.582,57.298 217.17,57.885 v1(217.17,59.44) 217.141,59.469 216.161,59.469 C57.1@216.132,59.498 216.132,59.495 215.907,59.27 U14.6@214.212,59.27
12V: C32.1 C35.2 C64.1 D18.2 Q8.2 R25.2 R63.1 R79.1 U2.12 | length 201.1
  Top Layer w0.5: v1(144.866,5.08) 210.09,5.08 v1(211.956,6.946)
  Mid-Layer 1 w0.5: v2(137.908,50.362) 137.908,36.331 145.434,28.805 v4@145.434,14.13 ; v1(144.866,5.08) 144.916,5.13 144.916,13.258 145.434,13.777 v4(145.434,13.885) ; v3(209.261,42.794) 209.311,42.744 209.311,37.922 212.371,34.862 v3(212.371,34.791) 212.371,34.72 211.956,34.305 v1(211.956,6.946)
  Bottom Layer w0.5: R79.1@102.14,54.026 102.214,53.952 102.214,53.06 102.275,53 102.275,52.36 Q8.2@102.325,52.31 102.329,52.307 C64.1@104.342,52.307 ; C64.1@104.346,52.304 106.287,50.362 v2(137.908,50.362) ; v4(145.434,13.885) v4@145.447,13.872 ; R63.1@145.46,12.889 145.447,12.902 v4@145.447,13.872 ; v4@145.511,13.808 v4@145.447,13.872 ; U2.12@207.786,35.553 209.374,35.553 C32.1@209.594,35.334 ; R25.2@208.349,42.807 208.355,42.801 209.255,42.801 v3(209.261,42.794) ; C32.1@209.424,35.503 C32.1@209.594,35.334 ; D18.2@213.181,32.988 213.181,34.038 212.428,34.791 v3(212.371,34.791) 212.36,34.791 211.892,35.259 211.242,35.259 C35.2@211.167,35.334 C32.1@209.594,35.334
30V: C76.1 L4.2 pad.1@214.397,54.73 R17.2 R48.2 | length 1.6
  Bottom Layer w0.5: R48.2@202.993,55.582 v1(203.806,55.582) 203.812,55.576 204.619,55.576 R17.2@204.625,55.569
AUX_15V: C23.1 C27.1 C30.2 C51.1 C59.1 R51.2 R74.2 R81.2 U1.1 U3.12 U4.1 U9.1 U13.5 | length 273.6
  Top Layer w0.5: v6(99.878,88.722) 99.928,88.671 102.823,88.671 106.943,84.552 109.875,84.552 v4(109.952,84.475)
  Mid-Layer 1 w0.5: v4(109.952,84.475) 110.028,84.399 110.028,81.215 111.125,80.118 v2(111.125,80.01)
  Mid-Layer 1 w0.8: v8(74.676,49.53) 72.564,47.418 72.577,30.727 89.898,13.407 v1(111.526,13.407) 111.526,8.159 112.572,7.112 127.761,7.112 ; v2(127.785,75.275) 127.785,75.248 127.675,75.139 127.675,30.162 127.761,30.076 127.761,7.112 ; v2(139.451,7.112) 127.761,7.112
  Bottom Layer w0.381: v8(74.676,49.53) v8@74.737,49.469 ; C30.2@75.389,49.469 C30.2@75.565,49.293 75.697,49.425 U3.12@77.412,49.425
  Bottom Layer w0.5: v8@74.737,49.469 C30.2@75.389,49.469 ; R74.2@97.957,90.728 97.957,89.702 97.235,88.98 97.235,88.78 98.917,88.78 C27.1@98.922,88.784 98.953,88.753 99.846,88.753 v6(99.878,88.722) ; R81.2@98.679,58.585 98.651,58.613 98.651,59.901 98.623,59.929 98.674,59.979 98.674,62.078 99.659,63.063 102.386,63.063 103.128,62.322 109.947,62.322 120.126,52.143 127.269,52.143 127.567,51.845 v7(127.675,51.845) ; U9.1@109.654,87.692 109.654,85.992 C59.1@109.976,85.67 109.964,85.658 109.964,84.487 v4(109.952,84.475) ; v2(111.125,80.01) 115.318,75.823 115.866,75.275 v2(127.785,75.275) ; U1.1@111.321,16.532 111.321,14.801 C23.1@111.517,14.605 111.521,14.601 111.521,13.411 v1(111.526,13.407) v1@111.596,13.407 ; R51.2@132.76,14.13 132.76,14.105 131.793,13.138 131.793,8.654 133.258,7.189 139.374,7.189 v2@139.426,7.137 ; v2(139.451,7.112) v2@139.426,7.137 ; U4.1@139.678,11.336 139.668,11.326 139.668,9.326 C51.1@139.401,9.059 139.426,9.034 v2@139.426,7.137
BLK: C17.1 R2.2 R29.1 U2.4 | length 60.2
  Mid-Layer 1 w0.7: v13(175.286,45.145) 175.286,45.128 176.285,44.129 v10@176.276,32.893
  Bottom Layer w0.5: v10(176.285,32.855) 176.31,32.831 186.574,32.831 187.246,33.503 195.085,33.503 196.577,34.995 v3(196.648,34.995) 196.698,35.045 197.36,35.045 197.41,35.095 197.734,35.095 R2.2@197.739,35.09 C17.1@199.517,35.09 199.517,35.065 199.742,34.84 200.652,34.84 201.209,34.283 U2.4@202.386,34.283
  Bottom Layer w0.7: R29.1@155.176,45.145 v13(175.286,45.145)
BW: C20.1 R9.1 R12.2 U2.8 | length 6.9
  Bottom Layer w0.5: R9.1@197.998,42.794 R12.2@199.853,42.794 199.878,42.794 200.424,42.248 200.424,42.069 201.1,41.394 201.812,41.394 C20.1@202.037,41.169 202.071,41.135 202.071,39.413 202.121,39.363 U2.8@202.386,39.363
COMP: C34.1 Q11.2 R42.1 U3.5 | length 18.7
  Mid-Layer 1 w0.508: v5(89.416,49.802) 89.433,49.784 89.433,45.364 92.558,42.24 v5(92.558,42.215)
  Bottom Layer w0.508: U3.5@82.862,49.425 82.879,49.443 84.559,49.443 85.396,50.28 87.287,50.28 87.79,49.777 87.79,49.145 C34.1@87.884,49.052 R42.1@89.416,49.052 v5(89.416,49.802) ; Q11.2@91.357,42.305 Q11.2@91.342,42.319 92.067,42.319 92.154,42.233 92.54,42.233 v5(92.558,42.215)
CS: C4.2 C5.2 C61.2 D3.4 R7.2 R8.2 R30.1 | length 11.4
  Bottom Layer w0.508: R7.2@67.34,37.69 67.34,42.811 70.79,46.261 72.13,46.261 R30.1@72.14,46.271
EARTH: C6.2 C11.1 C47.2 C49.1 J3.3
G1: R61.1 U7.1 | length 1.9
  Bottom Layer w0.6: R61.1@151.137,90.001 151.262,90.001 151.818,90.557 U7.1@152.773,90.557
G2: R60.2 U8.1 | length 2
  Bottom Layer w0.6: R60.2@171.907,90.003 172.032,90.003 172.692,90.663 U8.1@173.659,90.663
Gate_A: R54.1 R57.1 U1.5 | length 5
  Bottom Layer w0.8: U1.5@111.321,19.282 111.848,19.809 111.848,21.289 112.083,21.524 R54.1@112.083,21.689 112.076,21.696 112.076,23.995 R57.1@112.069,24.002
Gate_B: R4.1 R13.1 U9.5 | length 4.2
  Bottom Layer w0.8: U9.5@109.654,90.442 111.529,90.442 R4.1@111.567,90.48 111.555,90.492 111.555,92.689 R13.1@111.542,92.702
GDA: R58.1 U3.14 | length 56.1
  Mid-Layer 1 w0.381: v5(76.327,51.973) 76.327,52.032 75.255,53.104 75.255,54.106 77.274,54.106 77.964,53.416 77.964,44.744 90.273,32.435 90.273,28.829 100.557,18.545 104.568,18.545 v4(104.596,18.516)
  Bottom Layer w0.381: v5(76.327,51.973) 76.331,51.969 77.408,51.969 U3.14@77.412,51.965 ; v4(104.596,18.516) 104.618,18.539 105.754,18.539 R58.1@105.777,18.561
GDB: R59.2 U3.11 | length 69.4
  Top Layer w0.5: v2(75.641,85.438) 86.216,85.438 87.384,84.269 103.037,84.269 104.055,85.288 v6(104.084,85.288)
  Mid-Layer 1 w0.5: v2(75.641,85.438) 75.641,85.329 74.284,83.972 74.284,52.897 76.268,50.913 76.268,48.652 76.119,48.503 76.119,48.174 v5(76.1,48.155)
  Bottom Layer w0.5: v5(76.1,48.155) U3.11@77.412,48.155
HO: D7.2 Q13.1 U2.15 | length 42.7
  Bottom Layer w0.5: Q13.1@171.688,17.883 171.738,17.933 171.738,19.406 172.215,19.883 D7.2@173.617,19.883 174.095,19.883 181.264,27.052 201.8,27.052 206.503,31.755 207.775,31.755 U2.15@207.786,31.743
I_OUT: R69.1 U14.1 | length 15
  Mid-Layer 1 w0.5: v1(201.93,64.389) 201.936,64.383 201.936,63.716 202.03,63.622 ; 201.98,63.677 202.03,63.627 202.03,63.622 ; v1(207.866,59.201) 207.816,59.251 206.401,59.251 202.03,63.622
  Bottom Layer w0.5: R69.1@200.821,64.43 200.841,64.409 201.91,64.409 v1(201.93,64.389) ; v1(207.866,59.201) 207.937,59.201 209.253,57.885 210.991,57.885 211.526,58.42 211.526,59.22 211.476,59.27 U14.1@211.462,59.27
ISNS: C19.1 C39.2 R3.2 U2.6 | length 19.1
  Bottom Layer w0.5: C39.2@185.423,35.022 185.454,35.052 192.114,35.052 195.24,38.178 197.771,38.178 C19.1@198.021,38.428 198.039,38.411 199.757,38.411 R3.2@199.774,38.393 199.939,38.393 200.874,37.459 200.874,37.276 201.276,36.873 202.336,36.873 U2.6@202.386,36.823
LDO_IN: C16.1 C52.1 C60.1 D11.1 R56.2 U2.3 U4.8 | length 130.3
  Top Layer w0.5: v1(142.31,7.943) 144.041,6.212 v1(199.665,6.212) ; v4(190.246,38.608) v4@190.277,38.577 ; v3@199.34,31.165 v3(199.39,31.115)
  Top Layer w1: v4(190.246,38.608) 194.432,42.794 197.911,42.794 C60.1@199.738,44.621
  Mid-Layer 1 w0.5: v1(142.31,7.943) v3(142.31,16.475) ; v4(190.246,38.608) 190.323,38.531 190.323,31.125 190.409,31.039 v1(190.409,30.968) ; v3(199.39,31.115) 199.39,31.044 199.665,30.769 v1(199.665,6.212)
  Bottom Layer w0.5: U4.8@139.678,16.586 C52.1@141.459,16.586 C52.1@141.465,16.58 ; R56.2@141.47,14.685 141.465,14.69 C52.1@141.465,16.58 ; v3(142.31,16.475) 142.26,16.525 141.52,16.525 C52.1@141.465,16.58 ; v4(190.246,38.608) D11.1@190.246,39.621 ; v1(190.409,30.968) 190.48,30.968 191.457,29.991 198.195,29.991 199.319,31.115 v3(199.39,31.115) ; C16.1@199.459,31.854 200.209,31.854 201.368,33.013 202.346,33.013 202.366,32.993 U2.3@202.386,33.013
LL/SS: C31.1 R25.1 R32.2 R70.2 U2.9 | length 7.2
  Bottom Layer w0.5: U2.9@207.786,39.363 208.261,39.363 208.311,39.413 208.311,39.888 208.349,39.926 R25.1@208.349,41.207 208.378,41.237 209.957,41.237 R32.2@209.986,41.266 C31.1@211.561,41.266 R70.2@211.562,42.87
LO: D8.2 Q14.1 U2.10 | length 54.9
  Bottom Layer w0.6: Q14.1@190.881,15.144 193.313,15.144 D8.2@193.411,15.045 214.475,15.045 216.027,16.597 216.027,37.002 214.931,38.098 211.598,38.098 211.594,38.093 U2.10@207.786,38.093
NetA: D9.1 D10.1 R28.1 R31.1 | length 117.6
  Bottom Layer w0.5: D9.1@59.741,93.756 D10.1@59.741,89.057 59.81,89.126 68.014,89.126 80.116,77.024 R28.1@89.94,77.024 105.445,77.024 109.287,73.182 124.574,73.182 142.638,55.118 R31.1@158.488,55.118
NetC1A_1: C1A.1 C1B.1 C1C.1 Q10.2 RT1.2
NetC2_2: C2.2 C3.1 C39.1 C40.1 T1.4 T1.5 | length 16.3
  Bottom Layer w1: C39.1@182.523,35.022 C40.1@182.523,37.638
  Bottom Layer w1.5: 168.883,37.638 C40.1@182.523,37.638
NetC4_1: C4.1 D3.1 L2.1 L8.1
NetC6_1: C6.1 C9.1 F1.2 L3.1 RV1.2 | length 10.3
  Top Layer w1.778: F1.2@5.613,25.845 8.043,28.274 C6.1@14.91,28.274
NetC9_2: C9.2 C11.2 J3.2 L3.2 RV1.1
NetC10_1: C10.1 C47.1 L3.4 L5.1
NetC10_2: C10.2 C49.2 L3.3 L5.2
NetC15_1: C15.1 D2.2 Q11.1 R15.2 | length 6.4
  Bottom Layer w0.508: Q11.1@91.342,44.219 91.323,44.238 91.323,45.714 C15.1@91.305,45.733 91.33,45.733 91.551,45.954 91.551,47.733 D2.2@92.197,48.379 92.486,48.668 93.944,48.668 R15.2@93.955,48.679
NetC18_1: C18.1 U2.5 U6.4 | length 15.2
  Bottom Layer w0.5: C18.1@199.416,36.733 199.441,36.733 200.132,36.042 200.73,36.042 201.169,35.603 202.336,35.603 U2.5@202.386,35.553 202.436,35.603 204.067,35.603 205.696,37.232 205.696,41.394 206.433,42.13 U6.4@206.433,44.621
NetC21_1: C21.1 R39.1 R41.1 U3.4 | length 18.1
  Mid-Layer 1 w0.508: v9@76.722,58.545 82.289,58.545 85.15,55.685 85.15,51.699 v9(85.167,51.681)
  Bottom Layer w0.508: R41.1@76.786,59.238 76.699,59.151 76.699,58.53 v9(76.682,58.513) 76.699,58.495 76.699,57.933 R39.1@76.899,57.734 ; U3.4@82.862,50.695 82.879,50.713 84.199,50.713 84.539,51.053 v9(85.167,51.681) 85.217,51.731 C21.1@85.242,51.731
NetC24_1: C24.1 R24.1 U3.16 | length 3.9
  Bottom Layer w0.508: R24.1@73.559,54.487 73.587,54.459 75.226,54.459 C24.1@75.255,54.431 75.312,54.487 77.394,54.487 U3.16@77.412,54.505
NetC25_1: C25.1 R26.1 U3.1 | length 4.1
  Bottom Layer w0.508: U3.1@82.862,54.505 83.262,54.505 83.451,54.695 C25.1@83.451,56.316 83.381,56.387 83.381,57.963 R26.1@83.31,58.033
NetC26_1: C26.1 D18.1 U2.14 | length 8.2
  Bottom Layer w0.5: U2.14@207.786,33.013 209.634,33.013 210.142,32.505 210.142,31.501 C26.1@210.287,31.356 210.412,31.356 211.212,30.556 212.546,30.556 213.081,30.02 213.081,29.088 D18.1@213.181,28.988
NetC28_1: C28.1 R76.2 R77.2 R83.1 | length 6.9
  Bottom Layer w0.5: C28.1@93.563,85.225 93.563,83.342 R77.2@93.275,83.055 93.275,82.954 93.675,82.554 R83.1@95.513,82.554 95.625,82.443 97.443,82.443 R76.2@97.554,82.331
NetC29_1: C29.1 R30.2 U3.10 | length 5.7
  Bottom Layer w0.508: R30.2@72.14,47.871 C29.1@73.818,47.871 75.005,47.871 75.973,46.903 77.394,46.903 U3.10@77.412,46.885
NetC33_1: C33.1 R34.1 R35.2 U3.2 | length 6.5
  Bottom Layer w0.508: U3.2@82.862,53.235 83.312,53.235 84.801,54.724 85.007,54.724 C33.1@85.228,54.945 R35.2@85.228,56.469 85.247,56.488 85.247,58.355 R34.1@85.266,58.374
NetC36_1: C36.1 R42.2 | length 1.5
  Bottom Layer w0.5: C36.1@87.914,47.452 R42.2@89.416,47.452
NetC37_1: C37.1 R11.2 R37.1 U3.9 | length 6.1
  Bottom Layer w0.508: R37.1@77.135,43.887 77.135,43.862 76.581,43.308 75.618,43.308 R11.2@75.397,43.087 C37.1@75.397,44.684 75.422,44.684 76.336,45.597 77.394,45.597 U3.9@77.412,45.615
NetC41_1: C41.1 D6.1 R33.2 R88.1 U3.7 | length 29.2
  Bottom Layer w0.4: 80.703,35.058 80.761,35.116 80.761,38.97 D6.1@80.861,39.07 83.139,41.348
  Bottom Layer w0.5: R33.2@80.158,23.749 80.149,23.758 80.149,25.519 81.174,26.543 81.174,30.508 80.703,30.979 80.703,35.058
  Bottom Layer w0.508: U3.7@82.862,46.885 82.879,46.867 84.973,46.867 85.632,46.208 85.632,44.881 R88.1@85.703,44.81 85.71,44.803 85.71,43.272 C41.1@85.717,43.265 85.694,43.242 85.694,42.287 84.755,41.348 83.139,41.348
NetC42_1: C42.1 R49.1 | length 2.2
  Bottom Layer w0.5: C42.1@199.829,53.943 199.864,53.977 199.864,56.055 R49.1@199.898,56.089
NetC42_2: C42.2 C50.2 R47.1 U5.1 U6.2 | length 13.9
  Bottom Layer w0.5: U5.1@196.628,55.308 196.631,55.305 198.189,55.305 C50.2@198.192,55.302 198.217,55.277 198.217,52.922 198.713,52.426 201.004,52.426 201.429,52.851 C42.2@201.429,53.943 R47.1@204.63,53.944 204.597,53.911 204.597,52.781 204.056,52.241 U6.2@203.893,52.241
NetC43_1: C43.1 R46.1 R90.2 U3.8 | length 26.1
  Mid-Layer 1 w0.508: v8(84.201,44.831) 84.238,44.868 84.718,44.868 85.979,46.128 85.979,62.45 87.317,63.788 v4(87.317,63.894)
  Bottom Layer w0.508: U3.8@82.862,45.615 82.766,45.615 82.723,45.573 82.723,44.129 C43.1@82.585,43.99 R90.2@84.176,43.99 84.189,44.003 84.189,44.819 v8(84.201,44.831)
  Bottom Layer w0.708: v4(87.317,63.894) R46.1@88.544,63.894
NetC44_2: C44.2 R52.2
NetC45_2: C45.2 R53.2 | length 2.4
  Bottom Layer w1: R53.2@154.924,75.184 154.924,75.309 155.276,75.661 C45.2@155.276,77.409
NetC50_1: C50.1 R48.1 R49.2 R50.2 U5.2 | length 11.6
  Bottom Layer w0.5: R50.2@193.163,55.289 193.172,55.299 194.718,55.299 U5.2@194.728,55.308 194.749,55.33 194.749,56.13 195.127,56.508 196.728,56.508 197.178,56.958 198.136,56.958 C50.1@198.192,56.902 198.192,56.927 198.883,57.618 199.826,57.618 R49.2@199.898,57.689 199.962,57.753 202.422,57.753 202.743,57.432 202.768,57.432 202.993,57.207 R48.1@202.993,57.182
NetC53_1: C53.1 U7.3 | length 1.7
  Bottom Layer w0.5: U7.3@154.673,90.557 154.687,90.571 154.687,92.216 C53.1@154.701,92.23
NetC54_1: C54.1 U8.3 | length 1.7
  Bottom Layer w0.5: C54.1@175.425,92.331 175.559,92.197 U8.3@175.559,90.663
NetC58_1: C58.1 R58.2 U1.3 | length 3.9
  Bottom Layer w0.5: R58.2@105.777,16.961 C58.1@107.428,16.961 107.642,16.747 109.371,16.747 109.421,16.697 U1.3@109.421,16.532
NetC62_1: C62.1 R59.1 U9.3 | length 3.7
  Bottom Layer w0.5: R59.1@104.084,87.638 104.145,87.699 105.697,87.699 C62.1@105.758,87.759 105.792,87.726 107.72,87.726 U9.3@107.754,87.692
NetC63_1: C63.1 Q10.1 R5.1 R14.1
NetC64_2: C64.2 D14.1 R80.2 | length 4.2
  Bottom Layer w0.5: C64.2@104.346,53.904 D14.1@104.346,55.929 104.855,55.42 105.995,55.42 106.22,55.195 R80.2@106.22,55.17
NetC100_1: C100.1 R100.1 U7.5
NetC101_1: C101.1 R101.1 U8.5 | length 3.7
  Bottom Layer w0.6: R101.1@172.212,86.017 172.25,85.979 173.863,85.979 173.659,86.183 U8.5@173.659,87.913
NetD1_3: D1.3 L1.4 Q1.2 | length 52.9
  Mid-Layer 1 w1.8: Q1.2@114.345,85.595 114.345,85.56 113.83,85.045 113.83,63.663 116.848,60.645 D1.3@116.848,60.618
  Bottom Layer w1.8: L1.4@94.575,70.515 95.584,69.506 95.584,69.359 98.646,66.297 102.215,66.297 104.025,64.488 112.951,64.488 116.821,60.618 D1.3@116.848,60.618
NetD3_2: D3.2 D9.2 L5.4 | length 13.4
  Bottom Layer w1.27: D3.2@50.165,83.85 50.165,90.835 52.959,93.629 55.194,93.629 D9.2@55.321,93.756
NetD3_3: D3.3 D10.2 L5.3 | length 5.2
  Bottom Layer w1.2: D3.3@55.245,83.85 D10.2@55.245,88.981
  Bottom Layer w1.54: D10.2@55.245,88.981 D10.2@55.321,89.057
NetD4_1: D4.1 Q4.1 R62.1 | length 7.9
  Bottom Layer w0.5: R62.1@186.012,67.954 186.012,67.979 186.237,68.204 186.262,68.204 186.406,68.347 187.489,68.347 Q4.1@187.501,68.336 188.079,68.336 188.515,67.9 188.515,67.572 189.6,66.486 189.6,64.64 189.037,64.076 D4.1@189.037,63.542
NetD5_3: D5.3 L6.4 Q12.2 | length 53.7
  Top Layer w1.778: L6.4@94.575,5.364 94.575,7.536 97.459,10.419 111.525,10.419 112.226,11.121 112.472,11.121 113.812,12.46 113.812,15.478 114.316,15.983 114.316,16.832 Q12.2@114.345,16.861 114.345,16.902 110.973,20.274 110.973,33.668 114.787,37.482 D5.3@116.848,37.482
NetD6_2: D6.2 D15.2 R16.1 R18.2 | length 6.1
  Bottom Layer w0.381: D6.2@83.061,39.07 83.171,38.96 84.556,38.96 D15.2@84.879,38.638 ; R18.2@85.052,40.416 84.965,40.329 84.965,38.724 D15.2@84.879,38.638 ; R16.1@86.102,37.056 86.077,37.056 85.793,37.34 85.793,37.365 85.717,37.44 85.717,38.1 85.417,38.1 D15.2@84.879,38.638
NetD7_1: D7.1 R38.1 | length 2
  Bottom Layer w0.5: R38.1@176.892,17.877 D7.1@176.892,19.883
NetD8_1: D8.1 R40.1 | length 2.3
  Bottom Layer w0.5: R40.1@191.535,17.322 191.56,17.322 192.35,18.113 193.204,18.113 D8.1@193.411,18.32
NetD12_1: D12.1 R13.2 | length 2.8
  Bottom Layer w0.8: R13.2@113.574,92.702 113.675,92.601 D12.1@116.326,92.601
NetD12_2: D12.2 Q1.1 R4.2 R6.2 | length 7.9
  Bottom Layer w0.8: R4.2@113.599,90.48 113.678,90.401 D12.2@116.326,90.401 116.495,90.232 116.495,88.35 Q1.1@116.711,88.133
  Bottom Layer w1: Q1.1@116.711,88.133 116.963,88.133 118.35,86.746 118.655,86.746 R6.2@118.79,86.611
NetD13_1: D13.1 R57.2 | length 2.2
  Bottom Layer w0.8: R57.2@114.101,24.002 114.194,24.094 D13.1@116.245,24.094
NetD13_2: D13.2 Q12.1 R19.2 R54.2 | length 7.5
  Bottom Layer w0.8: R54.2@114.115,21.689 114.321,21.894 D13.2@116.245,21.894 116.245,21.771 116.495,21.521 116.495,19.615 Q12.1@116.711,19.399 116.95,19.399 118.523,17.826 R19.2@118.688,17.826
NetD20_1: D20.1 R74.1 U13.4 | length 3.3
  Bottom Layer w0.5: D20.1@94.225,88.74 94.242,88.758 95.313,88.758 U13.4@95.33,88.775 95.38,88.825 95.38,90.018 95.925,90.562 R74.1@95.925,90.728
NetF1_1: F1.1 J3.1
NetL7_6: L7.6 T1.2 T1.3
NetL8_2: L8.2 R91.1
NetQ2_1: Q2.1 Q14.2 R40.2 R45.2 | length 9.8
  Bottom Layer w0.5: Q2.1@186.405,19.121 186.678,18.848 186.678,18.352 187.675,17.355 R45.2@187.675,17.33 187.679,17.326 189.931,17.326 R40.2@189.935,17.322 189.91,17.322 189.685,17.097 189.685,17.072 189.6,16.987 189.6,13.691 190.047,13.244 Q14.2@190.841,13.244
NetQ3_1: Q3.1 Q13.2 R38.2 R44.2 | length 8.8
  Bottom Layer w0.5: R44.2@169.971,17.102 170.195,16.878 172.782,16.878 173.588,17.683 Q13.2@173.588,17.883 173.591,17.88 175.289,17.88 R38.2@175.292,17.877
  Bottom Layer w0.508: R38.2@175.286,17.883 R38.2@175.289,17.88
  Bottom Layer w0.8: Q3.1@168.132,19.171 168.132,18.965 169.971,17.127 R44.2@169.971,17.102
NetQ5_1: Q5.1 R60.1 | length 7.3
  Bottom Layer w0.8: Q5.1@171.112,82.452 170.103,83.461 170.103,87.248 170.839,87.984 171.888,87.984 R60.1@171.907,88.003
NetQ6_1: Q6.1 R63.2 R64.2 | length 3.2
  Bottom Layer w0.5: R63.2@143.86,12.889 143.857,12.886 143.857,11.357 Q6.1@143.853,11.354 143.903,11.304 145.251,11.304 R64.2@145.434,11.12
NetQ6_3: Q6.3 R56.1 U4.3 | length 8.4
  Bottom Layer w0.5: U4.3@137.138,11.336 137.147,11.346 137.147,12.411 137.757,13.021 141.406,13.021 R56.1@141.462,13.076 ; Q6.3@141.453,10.404 141.462,10.412 R56.1@141.462,13.076 ; R56.1@141.47,13.085 R56.1@141.462,13.076
NetQ7_1: Q7.1 R61.2 | length 7.5
  Bottom Layer w0.8: Q7.1@150.253,82.352 150.253,82.47 149.223,83.5 149.223,87.104 150.103,87.984 151.12,87.984 R61.2@151.137,88.001
NetQ8_1: Q8.1 Q9.3 R79.2 | length 3.8
  Bottom Layer w0.5: Q8.1@100.425,52.31 100.475,52.36 100.475,53.961 R79.2@100.54,54.026 100.565,54.026 100.79,54.251 100.79,54.915 101.409,55.534 Q9.3@101.409,55.734
NetQ8_3: Q8.3 R5.2 | length 1.8
  Bottom Layer w0.5: R5.2@101.216,48.197 101.375,48.356 Q8.3@101.375,49.91
NetQ9_1: Q9.1 R80.1 R81.1 R82.2 | length 10.6
  Bottom Layer w0.5: R81.1@98.679,56.985 98.717,56.947 99.472,56.947 Q9.1@100.459,57.934 ; R82.2@100.609,59.973 100.509,59.873 100.509,58.184 Q9.1@100.459,58.134 Q9.1@100.459,57.934 ; R80.1@106.22,56.77 106.22,56.795 105.995,57.02 101.373,57.02 Q9.1@100.459,57.934
NetR1_2: R1.2 U6.3 | length 2.1
  Bottom Layer w0.5: U6.3@203.893,44.621 203.893,44.541 204.788,43.646 204.788,42.955 R1.2@204.755,42.921
NetR10_1: R10.1 R22.2 | length 2.1
  Bottom Layer w0.5: R22.2@166.417,55.118 R10.1@168.546,55.118
NetR10_2: R10.2 U2.1 | length 52.6
  Top Layer w0.5: v2(188.15,29.411) 188.258,29.411 188.975,28.694 199.796,28.694 202.122,31.02 v8(202.176,31.02)
  Mid-Layer 1 w0.5: v1(186.062,47.187) 186.062,47.116 188.131,45.047 188.131,29.43 v2(188.15,29.411)
  Bottom Layer w0.5: R10.2@171.446,55.118 175.027,51.537 181.64,51.537 185.991,47.187 v1(186.062,47.187) v1@186.112,47.136 ; v8(202.176,31.02) 202.214,30.982 202.214,30.523 202.264,30.473 U2.1@202.386,30.473
NetR17_1: R17.1 R47.2 U6.1 | length 3.4
  Bottom Layer w0.5: R17.1@206.225,55.569 206.227,55.567 206.227,53.946 R47.2@206.23,53.944 206.331,53.842 206.331,52.343 U6.1@206.433,52.241
NetR20_1: R20.1 R27.2 | length 2.4
  Bottom Layer w0.5: R27.2@90.576,61.604 90.697,61.483 R20.1@92.888,61.483
NetR21_1: R21.1 R33.1 | length 3.1
  Bottom Layer w0.5: R21.1@80.137,18.669 80.158,18.69 R33.1@80.158,21.717
NetR21_2: R21.2 R23.1 | length 3.2
  Bottom Layer w0.5: R23.1@80.137,13.462 R21.2@80.137,16.637
NetR22_1: R22.1 R31.2 | length 2.1
  Bottom Layer w0.5: R31.2@161.388,55.118 R22.1@163.517,55.118
NetR27_1: R27.1 R34.2 | length 4.3
  Bottom Layer w0.5: R34.2@87.298,58.374 87.324,58.4 87.324,61.248 87.681,61.604 R27.1@88.544,61.604
NetR28_2: R28.2 R77.1 | length 3.3
  Bottom Layer w0.5: R28.2@89.94,79.924 89.975,79.924 90.375,80.324 R77.1@90.375,83.055
NetR29_2: R29.2 R36.1 | length 2.2
  Bottom Layer w1: R36.1@150.071,45.145 R29.2@152.276,45.145
NetR36_2: R36.2 R43.1 | length 2.2
  Bottom Layer w1: R43.1@144.966,45.145 R36.2@147.171,45.145
NetR46_2: R46.2 R86.1 | length 2.9
  Bottom Layer w0.5: R46.2@90.576,63.894 R86.1@93.523,63.894
NetR51_1: R51.1 R55.2 U4.7 | length 7.1
  Bottom Layer w0.5: R51.1@132.76,15.73 134.31,15.73 R55.2@134.335,15.705 ; R55.2@134.335,15.73 R55.2@134.335,15.705 ; U4.7@138.408,16.586 138.408,15.748 137.695,15.035 135.323,15.035 135.275,15.084 134.956,15.084 R55.2@134.335,15.705
NetR66_2: R66.2 U14.3 | length 3
  Bottom Layer w0.5: U14.3@211.462,61.17 211.479,61.187 212.036,61.187 212.362,61.513 212.362,62.422 212.307,62.477 212.307,62.707 211.812,63.202 R66.2@211.812,63.227
NetR67_1: R67.1 R68.1 R72.2 U11.3 | length 12.6
  Bottom Layer w0.5: R72.2@197.532,62.81 197.517,62.796 R68.1@197.517,61.148 ; U11.3@201.125,62.215 201.125,61.342 200.8,61.017 197.619,61.017 R68.1@197.503,61.133 R68.1@197.517,61.148 ; R67.1@202.815,61.919 202.43,62.304 201.207,62.304 201.2,62.311 200.928,62.039 200.928,61.507 200.633,61.212 197.582,61.212 R68.1@197.517,61.148
NetR67_2: R67.2 R73.1 U11.4 U12.2 | length 13.5
  Bottom Layer w0.5: U11.4@201.125,59.615 202.544,59.615 R67.2@202.815,59.887 205.035,59.887 208.261,56.66 208.261,53.946 R73.1@208.263,53.944 208.28,53.927 208.28,52.922 208.961,52.241 U12.2@209.125,52.241
NetR69_2: R69.2 U11.1 | length 2.2
  Bottom Layer w0.5: R69.2@199.221,64.43 199.223,64.428 199.223,62.217 U11.1@199.225,62.215
NetR70_1: R70.1 U12.4 | length 3.3
  Bottom Layer w0.5: U12.4@211.665,44.621 211.605,44.681 211.587,44.681 211.688,44.579 212.848,44.579 213.181,44.246 213.181,42.89 R70.1@213.162,42.871
NetR71_1: R71.1 R73.2 U12.1 | length 3.4
  Bottom Layer w0.5: R73.2@209.863,53.944 R71.1@211.502,53.943 211.502,52.404 U12.1@211.665,52.241
NetR75_1: R75.1 R83.2 U13.3 | length 4
  Bottom Layer w0.5: U13.3@95.33,86.025 95.33,84.338 R83.2@95.513,84.154 R75.1@97.554,84.154
NetR78_2: R78.2 U14.4 | length 3.1
  Bottom Layer w0.5: R78.2@213.388,63.227 213.163,63.002 213.163,62.575 213.065,62.477 213.065,61.561 213.406,61.22 214.162,61.22 U14.4@214.212,61.17
NetR86_2: R86.2 R87.1 | length 2.4
  Bottom Layer w0.5: R87.1@95.555,61.483 R86.2@95.555,63.894
NetR89_2: R89.2 U3.3 | length 2.9
  Bottom Layer w0.508: U3.3@82.862,51.965 83.851,51.965 85.217,53.332 R89.2@85.242,53.332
